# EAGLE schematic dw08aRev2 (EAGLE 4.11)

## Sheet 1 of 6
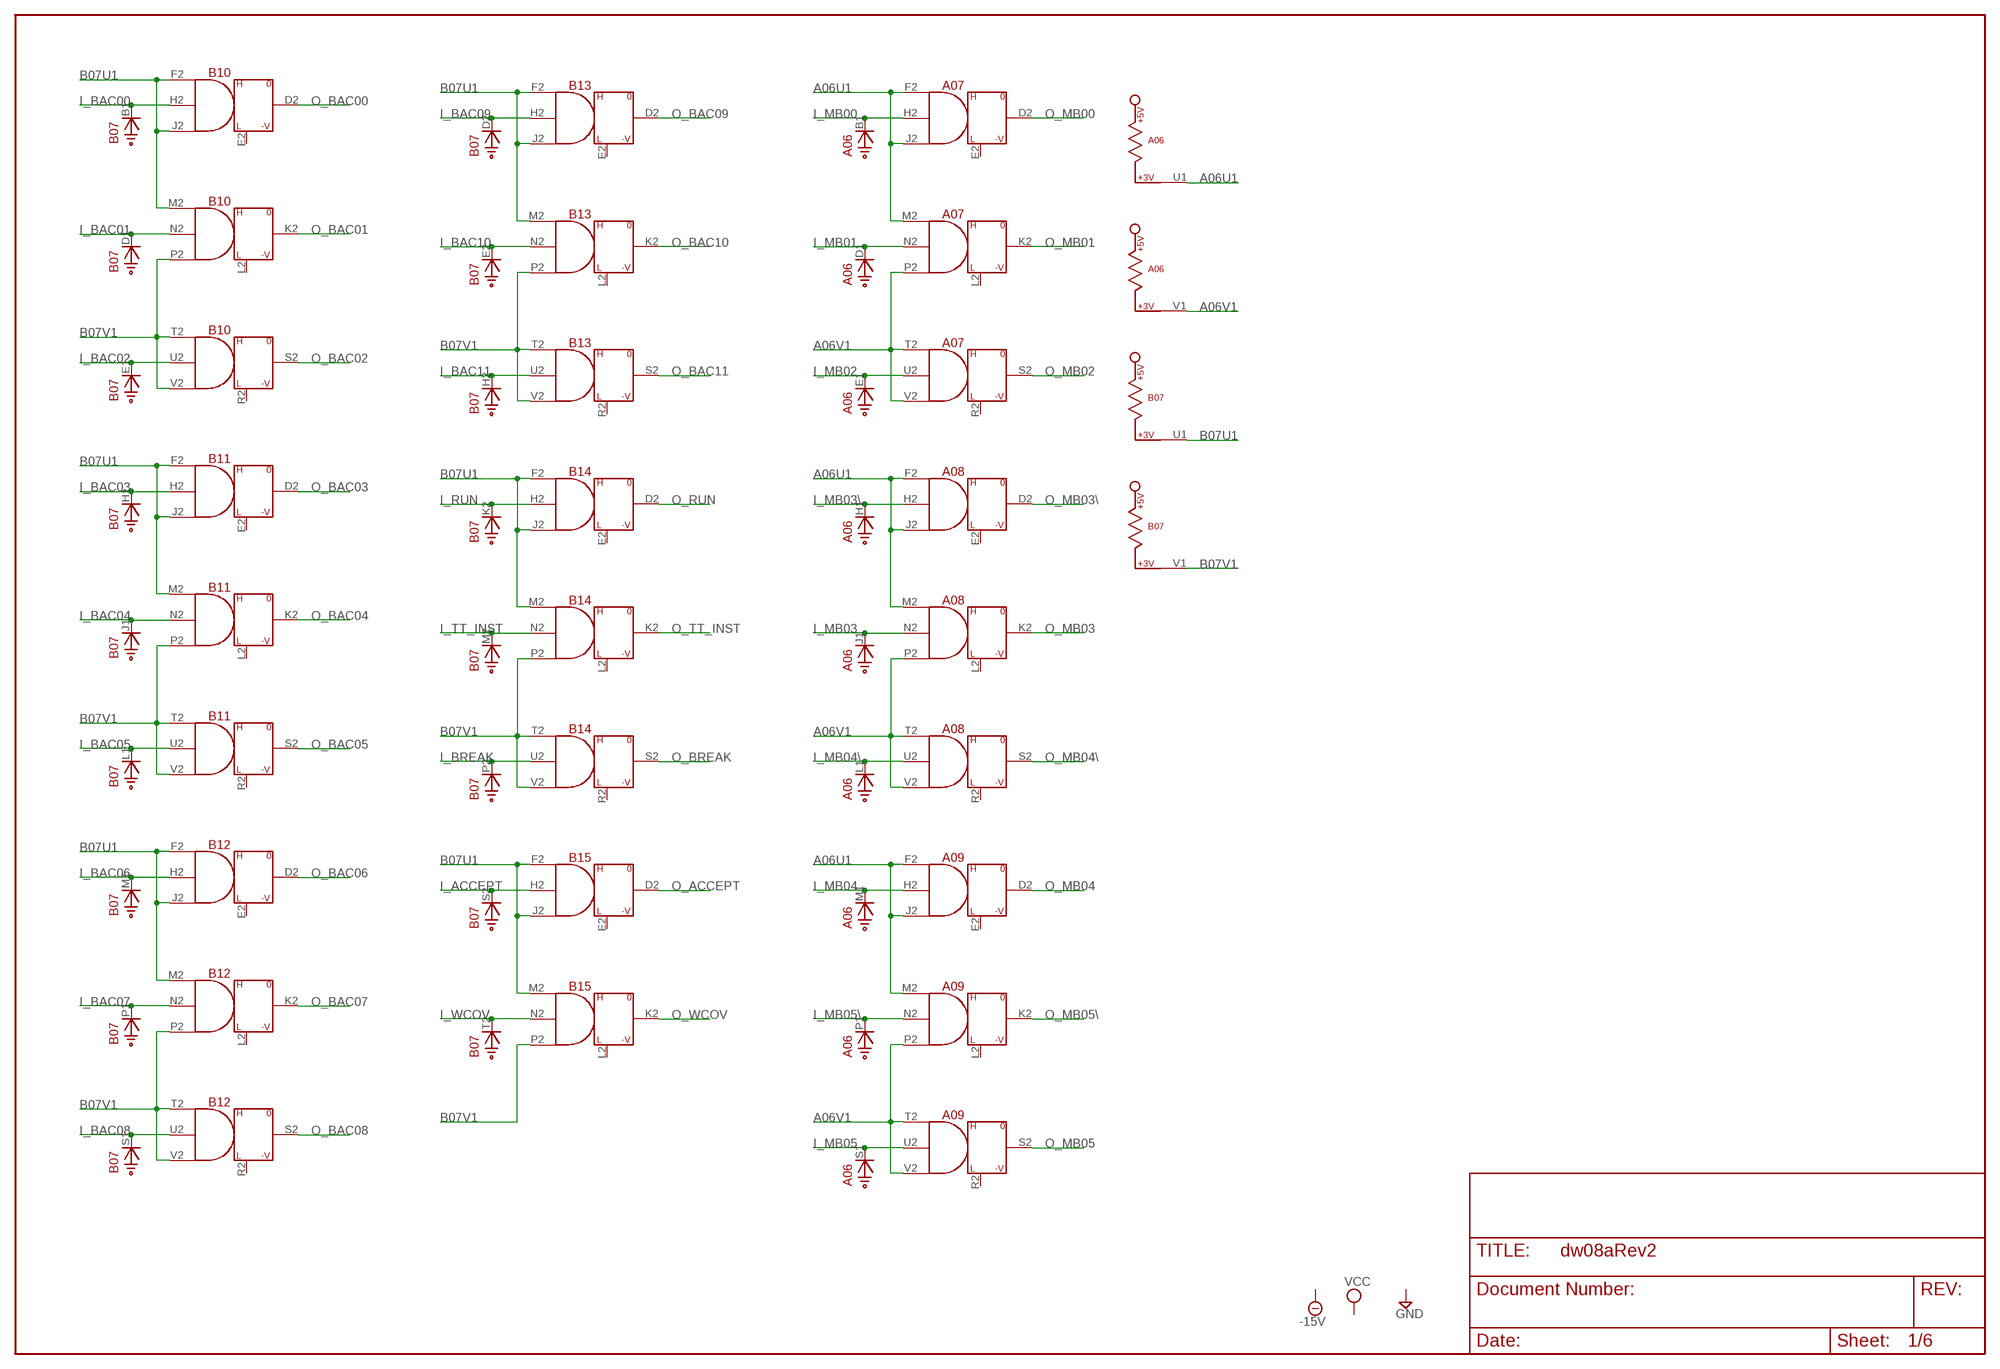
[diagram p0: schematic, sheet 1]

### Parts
A06  M907  [H807]
A07  M651  [H807]
A08  M651  [H807]
A09  M651  [H807]
B07  M907  [H807]
B10  M651  [H807]
B11  M651  [H807]
B12  M651  [H807]
B13  M651  [H807]
B14  M651  [H807]
B15  M651  [H807]

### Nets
A06U1: A06.U1 A07.F2(IN1) A07.J2(IN3) A07.M2(IN1) A08.F2(IN1) A08.J2(IN3) A08.M2(IN1) A09.F2(IN1) A09.J2(IN3) A09.M2(IN1) ; also sheet 2
A06V1: A06.V1 A07.P2(IN3) A07.T2(IN1) A07.V2(IN3) A08.P2(IN3) A08.T2(IN1) A08.V2(IN3) A09.P2(IN3) A09.T2(IN1) A09.V2(IN3) ; also sheet 2
B07U1: B07.U1 B10.F2(IN1) B10.J2(IN3) B10.M2(IN1) B11.F2(IN1) B11.J2(IN3) B11.M2(IN1) B12.F2(IN1) B12.J2(IN3) B12.M2(IN1) B13.F2(IN1) B13.J2(IN3) B13.M2(IN1) B14.F2(IN1) B14.J2(IN3) B14.M2(IN1) B15.F2(IN1) B15.J2(IN3) B15.M2(IN1) ; also sheet 2
B07V1: B07.V1 B10.P2(IN3) B10.T2(IN1) B10.V2(IN3) B11.P2(IN3) B11.T2(IN1) B11.V2(IN3) B12.P2(IN3) B12.T2(IN1) B12.V2(IN3) B13.P2(IN3) B13.T2(IN1) B13.V2(IN3) B14.P2(IN3) B14.T2(IN1) B14.V2(IN3) B15.P2(IN3)
I_ACCEPT: B07.S2(CATHODE) B15.H2(IN2) ; also sheet 6
I_BAC00: B07.B1(CATHODE) B10.H2(IN2) ; also sheet 6
I_BAC01: B07.D1(CATHODE) B10.N2(IN2) ; also sheet 6
I_BAC02: B07.E1(CATHODE) B10.U2(IN2) ; also sheet 6
I_BAC03: B07.H1(CATHODE) B11.H2(IN2) ; also sheet 6
I_BAC04: B07.J1(CATHODE) B11.N2(IN2) ; also sheet 6
I_BAC05: B07.L1(CATHODE) B11.U2(IN2) ; also sheet 6
I_BAC06: B07.M1(CATHODE) B12.H2(IN2) ; also sheet 6
I_BAC07: B07.P1(CATHODE) B12.N2(IN2) ; also sheet 6
I_BAC08: B07.S1(CATHODE) B12.U2(IN2) ; also sheet 6
I_BAC09: B07.D2(CATHODE) B13.H2(IN2) ; also sheet 6
I_BAC10: B07.E2(CATHODE) B13.N2(IN2) ; also sheet 6
I_BAC11: B07.H2(CATHODE) B13.U2(IN2) ; also sheet 6
I_BREAK: B07.P2(CATHODE) B14.U2(IN2) ; also sheet 4,6
I_MB00: A06.B1(CATHODE) A07.H2(IN2) ; also sheet 6
I_MB01: A06.D1(CATHODE) A07.N2(IN2) ; also sheet 6
I_MB02: A06.E1(CATHODE) A07.U2(IN2) ; also sheet 6
I_MB03: A06.J1(CATHODE) A08.N2(IN2) ; also sheet 6
I_MB03\: A06.H1(CATHODE) A08.H2(IN2) ; also sheet 6
I_MB04: A06.M1(CATHODE) A09.H2(IN2) ; also sheet 6
I_MB04\: A06.L1(CATHODE) A08.U2(IN2) ; also sheet 6
I_MB05: A06.S1(CATHODE) A09.U2(IN2) ; also sheet 6
I_MB05\: A06.P1(CATHODE) A09.N2(IN2) ; also sheet 6
I_RUN: B07.K2(CATHODE) B14.H2(IN2) ; also sheet 6
I_TT_INST: B07.M2(CATHODE) B14.N2(IN2) ; also sheet 6
I_WCOV: B07.T2(CATHODE) B15.N2(IN2) ; also sheet 6
O_ACCEPT: B15.D2(OUT) ; also sheet 5
O_BAC00: B10.D2(OUT) ; also sheet 5
O_BAC01: B10.K2(OUT) ; also sheet 5
O_BAC02: B10.S2(OUT) ; also sheet 5
O_BAC03: B11.D2(OUT) ; also sheet 5
O_BAC04: B11.K2(OUT) ; also sheet 5
O_BAC05: B11.S2(OUT) ; also sheet 5
O_BAC06: B12.D2(OUT) ; also sheet 5
O_BAC07: B12.K2(OUT) ; also sheet 5
O_BAC08: B12.S2(OUT) ; also sheet 5
O_BAC09: B13.D2(OUT) ; also sheet 5
O_BAC10: B13.K2(OUT) ; also sheet 5
O_BAC11: B13.S2(OUT) ; also sheet 5
O_BREAK: B14.S2(OUT) ; also sheet 5
O_MB00: A07.D2(OUT) ; also sheet 5
O_MB01: A07.K2(OUT) ; also sheet 5
O_MB02: A07.S2(OUT) ; also sheet 5
O_MB03: A08.K2(OUT) ; also sheet 5
O_MB03\: A08.D2(OUT) ; also sheet 5
O_MB04: A09.D2(OUT) ; also sheet 5
O_MB04\: A08.S2(OUT) ; also sheet 5
O_MB05: A09.S2(OUT) ; also sheet 5
O_MB05\: A09.K2(OUT) ; also sheet 5
O_RUN: B14.D2(OUT) ; also sheet 5
O_TT_INST: B14.K2(OUT) ; also sheet 5
O_WCOV: B15.K2(OUT) ; also sheet 5
Unconnected: A07.E2(SLOW) A07.L2(SLOW) A07.R2(SLOW) A08.E2(SLOW) A08.L2(SLOW) A08.R2(SLOW) A09.E2(SLOW) A09.L2(SLOW) A09.R2(SLOW) B07.V2(CATHODE) B10.E2(SLOW) B10.L2(SLOW) B10.R2(SLOW) B11.E2(SLOW) B11.L2(SLOW) B11.R2(SLOW) B12.E2(SLOW) B12.L2(SLOW) B12.R2(SLOW) B13.E2(SLOW) B13.L2(SLOW) B13.R2(SLOW) B14.E2(SLOW) B14.L2(SLOW) B14.R2(SLOW) B15.E2(SLOW) B15.L2(SLOW) B15.R2(SLOW) B15.S2(OUT) B15.T2(IN1) B15.U2(IN2) B15.V2(IN3)

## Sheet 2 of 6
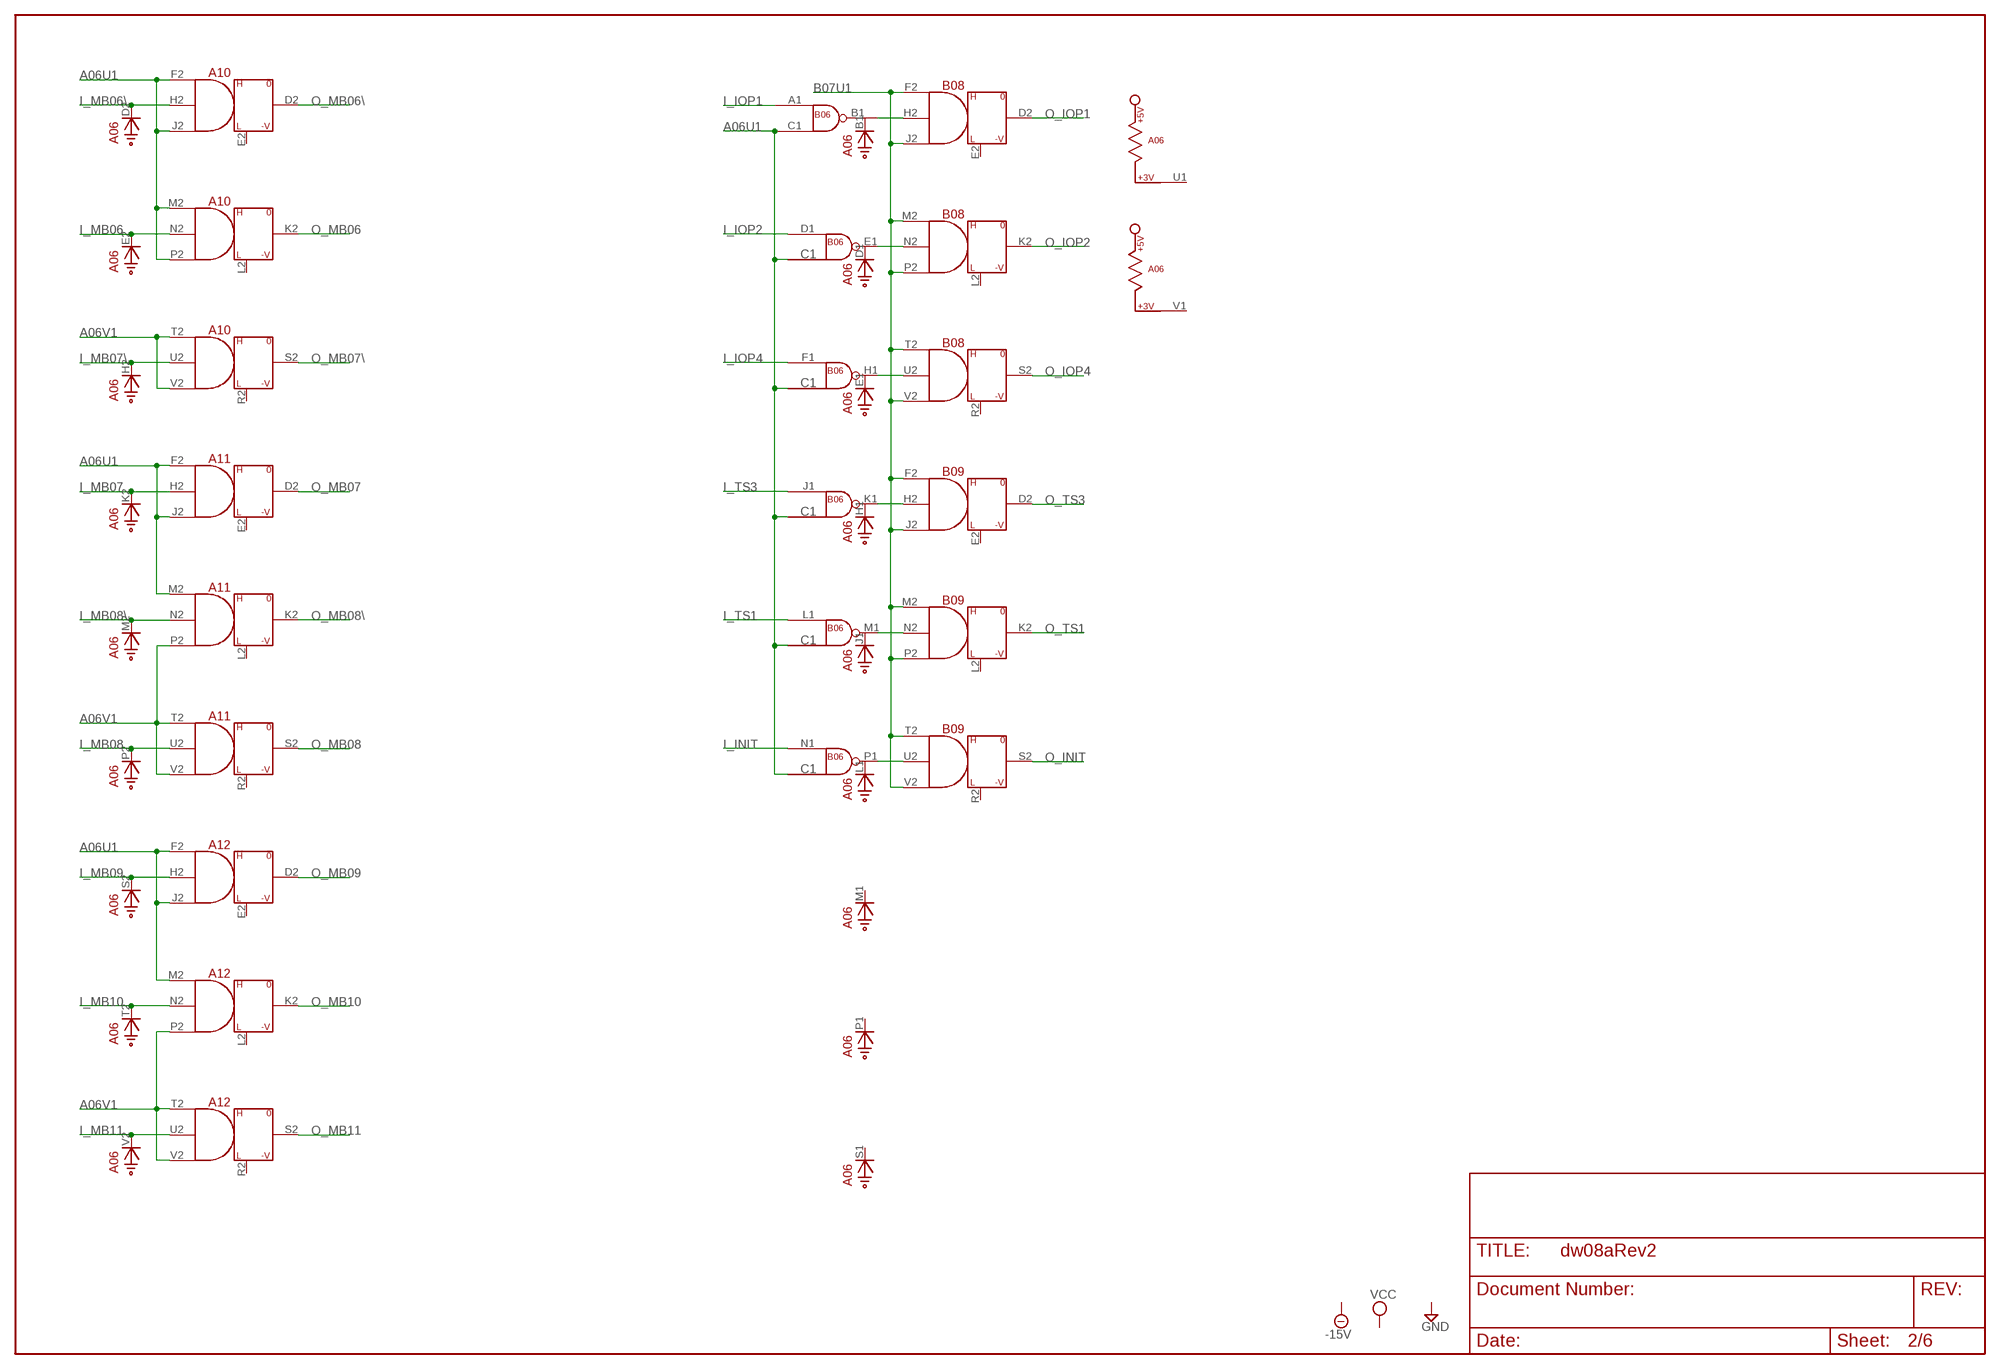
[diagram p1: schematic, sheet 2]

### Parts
A10  M651  [H807]
A11  M651  [H807]
A12  M651  [H807]
B06  M101  [H807]
B08  M651  [H807]
B09  M651  [H807]

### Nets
A06U1: A10.F2(IN1) A10.J2(IN3) A10.M2(IN1) A10.P2(IN3) A11.F2(IN1) A11.J2(IN3) A11.M2(IN1) A12.F2(IN1) A12.J2(IN3) A12.M2(IN1) B06.C1(IN2) ; also sheet 1
A06V1: A10.T2(IN1) A10.V2(IN3) A11.P2(IN3) A11.T2(IN1) A11.V2(IN3) A12.P2(IN3) A12.T2(IN1) A12.V2(IN3) ; also sheet 1
B07U1: B08.F2(IN1) B08.J2(IN3) B08.M2(IN1) B08.P2(IN3) B08.T2(IN1) B08.V2(IN3) B09.F2(IN1) B09.J2(IN3) B09.M2(IN1) B09.P2(IN3) B09.T2(IN1) B09.V2(IN3) ; also sheet 1
I_INIT: B06.N1(IN) ; also sheet 6
I_IOP1: B06.A1(IN1) ; also sheet 6
I_IOP2: B06.D1(IN) ; also sheet 6
I_IOP4: B06.F1(IN) ; also sheet 6
I_MB06: A06.E2(CATHODE) A10.N2(IN2) ; also sheet 6
I_MB06\: A06.D2(CATHODE) A10.H2(IN2) ; also sheet 6
I_MB07: A06.K2(CATHODE) A11.H2(IN2) ; also sheet 6
I_MB07\: A06.H2(CATHODE) A10.U2(IN2) ; also sheet 6
I_MB08: A06.P2(CATHODE) A11.U2(IN2) ; also sheet 6
I_MB08\: A06.M2(CATHODE) A11.N2(IN2) ; also sheet 6
I_MB09: A06.S2(CATHODE) A12.H2(IN2) ; also sheet 6
I_MB10: A06.T2(CATHODE) A12.N2(IN2) ; also sheet 6
I_MB11: A06.V2(CATHODE) A12.U2(IN2) ; also sheet 6
I_TS1: B06.L1(IN) ; also sheet 6
I_TS3: B06.J1(IN) ; also sheet 6
N$1: B06.B1(OUT) B08.H2(IN2)
N$2: B06.E1(OUT) B08.N2(IN2)
N$3: B06.H1(OUT) B08.U2(IN2)
N$4: B06.K1(OUT) B09.H2(IN2)
N$5: B06.M1(OUT) B09.N2(IN2)
N$6: B06.P1(OUT) B09.U2(IN2)
O_INIT: B09.S2(OUT) ; also sheet 5
O_IOP1: B08.D2(OUT) ; also sheet 5
O_IOP2: B08.K2(OUT) ; also sheet 5
O_IOP4: B08.S2(OUT) ; also sheet 5
O_MB06: A10.K2(OUT) ; also sheet 5
O_MB06\: A10.D2(OUT) ; also sheet 5
O_MB07: A11.D2(OUT) ; also sheet 5
O_MB07\: A10.S2(OUT) ; also sheet 5
O_MB08: A11.S2(OUT) ; also sheet 5
O_MB08\: A11.K2(OUT) ; also sheet 5
O_MB09: A12.D2(OUT) ; also sheet 5
O_MB10: A12.K2(OUT) ; also sheet 5
O_MB11: A12.S2(OUT) ; also sheet 5
O_TS1: B09.K2(OUT) ; also sheet 5
O_TS3: B09.D2(OUT) ; also sheet 5
Unconnected: A10.E2(SLOW) A10.L2(SLOW) A10.R2(SLOW) A11.E2(SLOW) A11.L2(SLOW) A11.R2(SLOW) A12.E2(SLOW) A12.L2(SLOW) A12.R2(SLOW) B06.E2(IN) B06.F2(OUT) B06.H2(IN) B06.J2(OUT) B06.K2(IN) B06.L2(OUT) B06.M2(IN) B06.N2(OUT) B06.P2(IN) B06.R1(IN) B06.R2(OUT) B06.S1(OUT) B06.S2(IN) B06.T2(OUT) B06.U1(OUT) B06.U2(IN) B06.V1(IN) B06.V2(OUT) B08.E2(SLOW) B08.L2(SLOW) B08.R2(SLOW) B09.E2(SLOW) B09.L2(SLOW) B09.R2(SLOW)

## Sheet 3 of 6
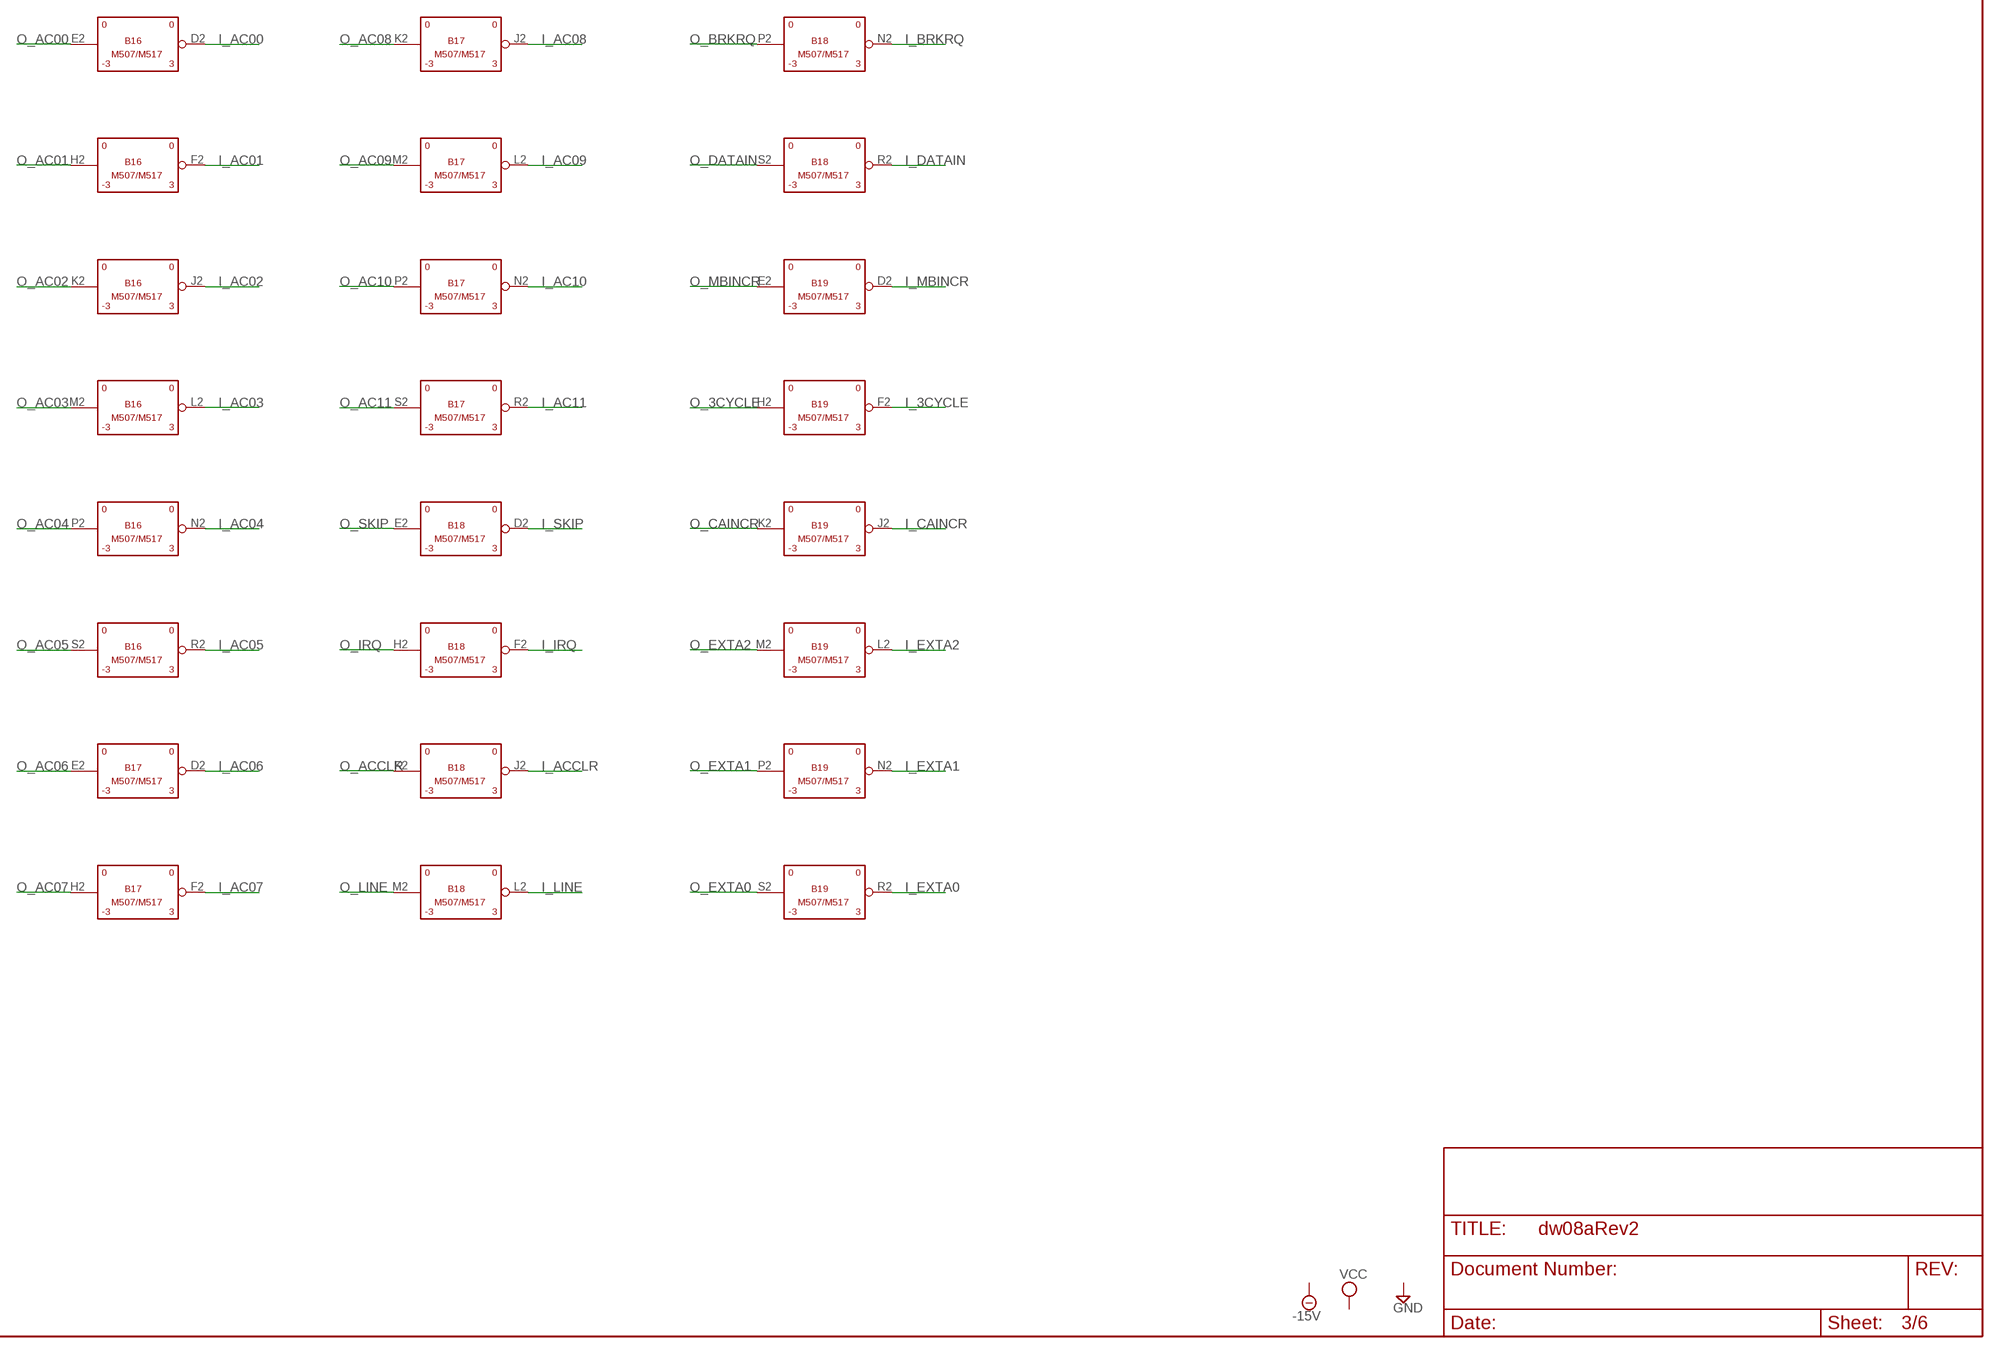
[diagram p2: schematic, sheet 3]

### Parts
B16  M517  [H807]
B17  M517  [H807]
B18  M517  [H807]
B19  M517  [H807]

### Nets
I_3CYCLE: B19.F2(OUT) ; also sheet 6
I_AC00: B16.D2(OUT) ; also sheet 6
I_AC01: B16.F2(OUT) ; also sheet 6
I_AC02: B16.J2(OUT) ; also sheet 6
I_AC03: B16.L2(OUT) ; also sheet 6
I_AC04: B16.N2(OUT) ; also sheet 6
I_AC05: B16.R2(OUT) ; also sheet 6
I_AC06: B17.D2(OUT) ; also sheet 6
I_AC07: B17.F2(OUT) ; also sheet 6
I_AC08: B17.J2(OUT) ; also sheet 6
I_AC09: B17.L2(OUT) ; also sheet 6
I_AC10: B17.N2(OUT) ; also sheet 6
I_AC11: B17.R2(OUT) ; also sheet 6
I_ACCLR: B18.J2(OUT) ; also sheet 6
I_BRKRQ: B18.N2(OUT) ; also sheet 6
I_CAINCR: B19.J2(OUT) ; also sheet 6
I_DATAIN: B18.R2(OUT) ; also sheet 6
I_EXTA0: B19.R2(OUT) ; also sheet 6
I_EXTA1: B19.N2(OUT) ; also sheet 6
I_EXTA2: B19.L2(OUT) ; also sheet 6
I_IRQ: B18.F2(OUT) ; also sheet 6
I_LINE: B18.L2(OUT) ; also sheet 6
I_MBINCR: B19.D2(OUT) ; also sheet 6
I_SKIP: B18.D2(OUT) ; also sheet 6
O_3CYCLE: B19.H2(IN) ; also sheet 5
O_AC00: B16.E2(IN) ; also sheet 5
O_AC01: B16.H2(IN) ; also sheet 5
O_AC02: B16.K2(IN) ; also sheet 5
O_AC03: B16.M2(IN) ; also sheet 5
O_AC04: B16.P2(IN) ; also sheet 5
O_AC05: B16.S2(IN) ; also sheet 5
O_AC06: B17.E2(IN) ; also sheet 5
O_AC07: B17.H2(IN) ; also sheet 5
O_AC08: B17.K2(IN) ; also sheet 5
O_AC09: B17.M2(IN) ; also sheet 5
O_AC10: B17.P2(IN) ; also sheet 5
O_AC11: B17.S2(IN) ; also sheet 5
O_ACCLR: B18.K2(IN) ; also sheet 5
O_BRKRQ: B18.P2(IN) ; also sheet 5
O_CAINCR: B19.K2(IN) ; also sheet 5
O_DATAIN: B18.S2(IN) ; also sheet 5
O_EXTA0: B19.S2(IN) ; also sheet 5
O_EXTA1: B19.P2(IN) ; also sheet 5
O_EXTA2: B19.M2(IN) ; also sheet 5
O_IRQ: B18.H2(IN) ; also sheet 5
O_LINE: B18.M2(IN) ; also sheet 5
O_MBINCR: B19.E2(IN) ; also sheet 5
O_SKIP: B18.E2(IN) ; also sheet 5

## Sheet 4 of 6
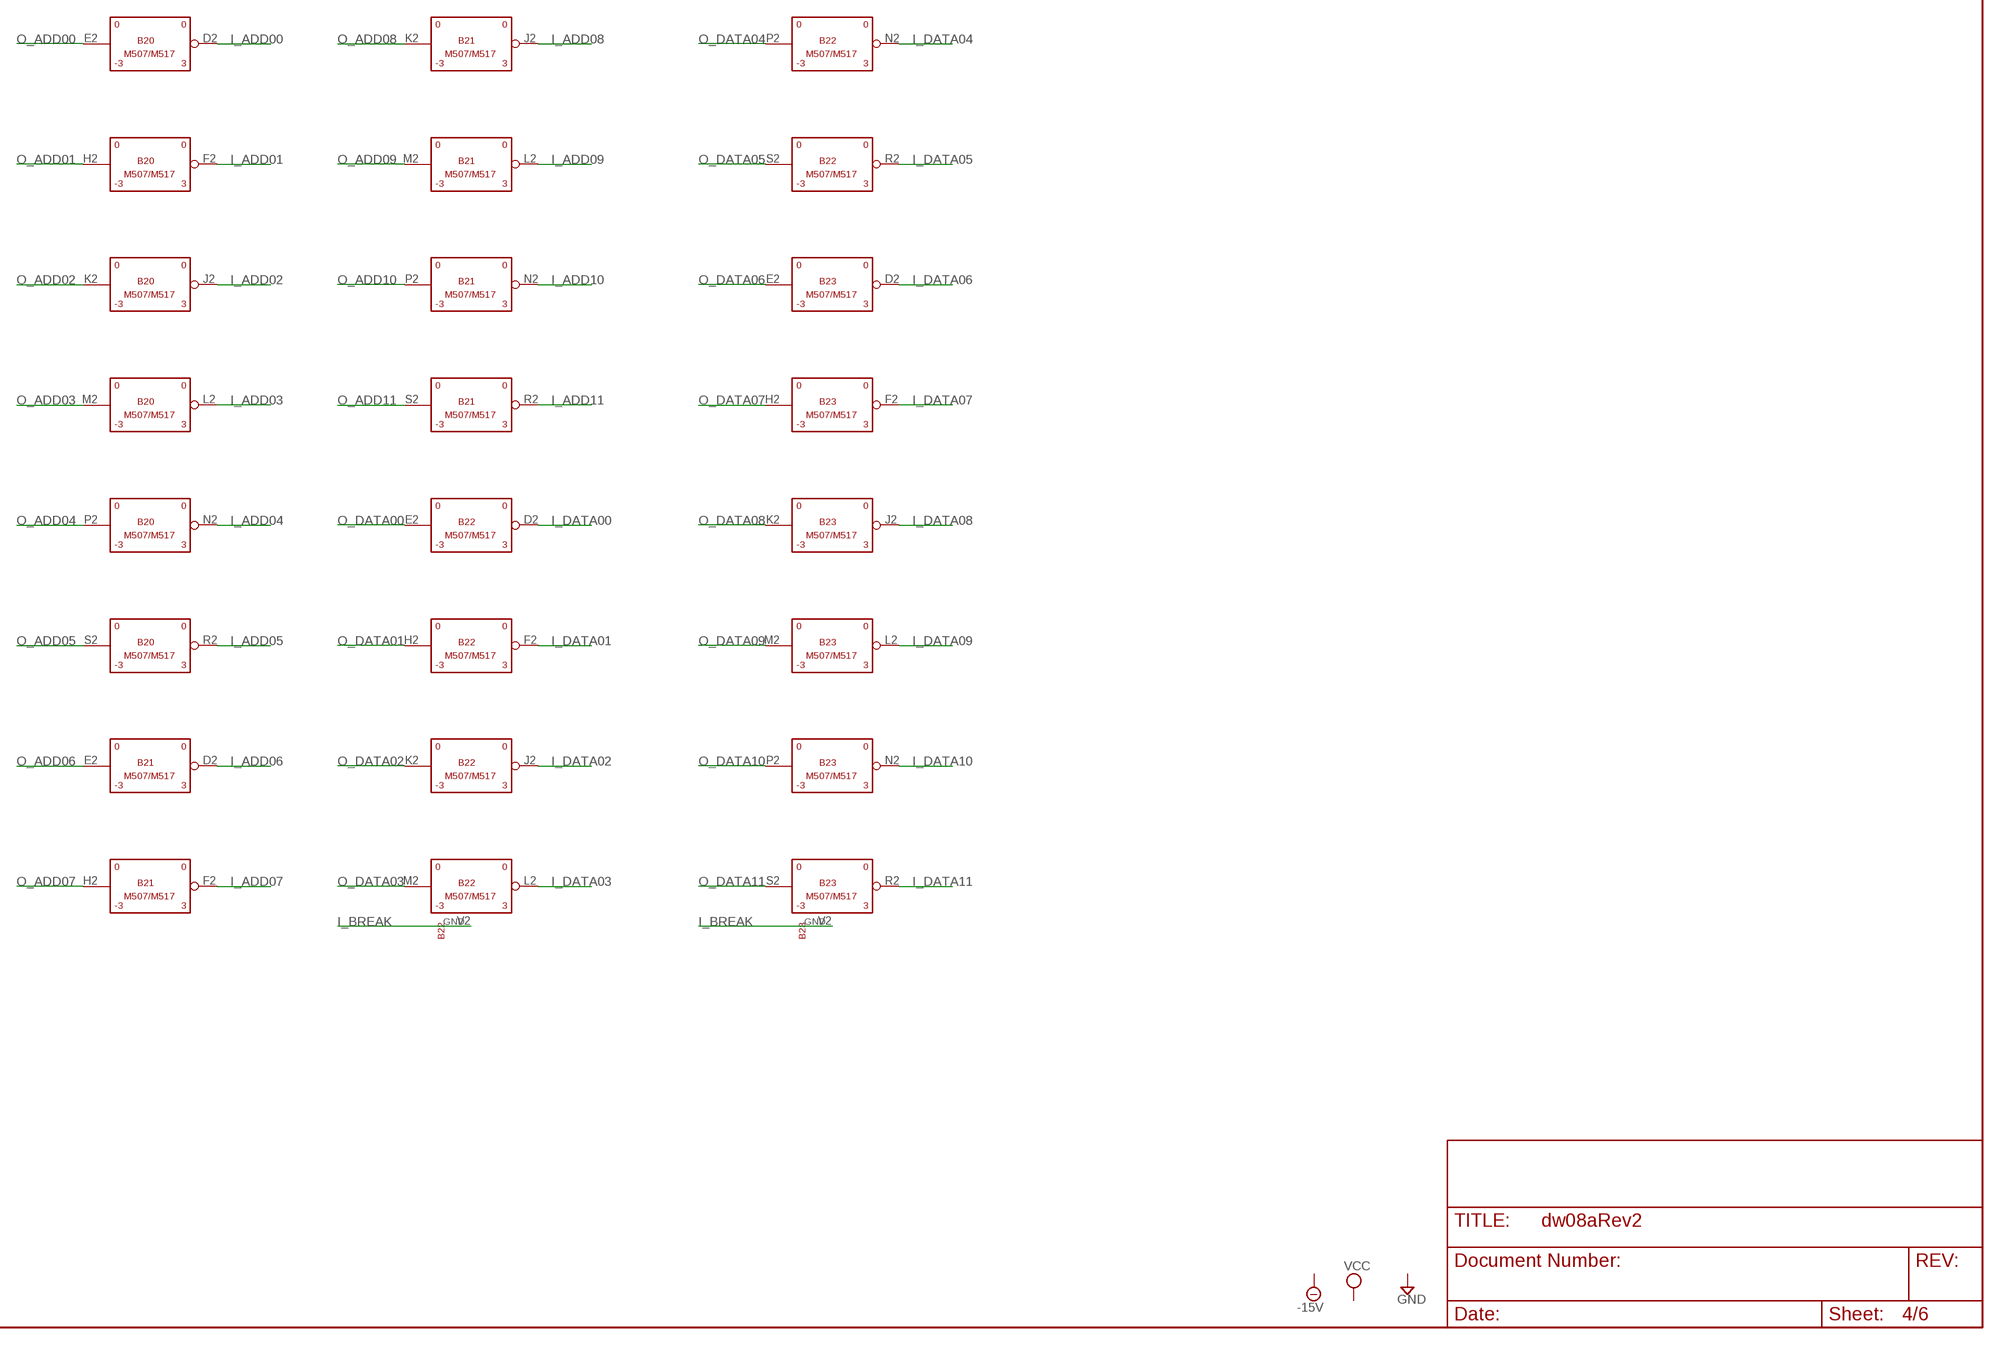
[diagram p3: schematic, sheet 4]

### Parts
B20  M517  [H807]
B21  M517  [H807]
B22  M517  [H807]
B23  M517  [H807]

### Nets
I_ADD00: B20.D2(OUT) ; also sheet 6
I_ADD01: B20.F2(OUT) ; also sheet 6
I_ADD02: B20.J2(OUT) ; also sheet 6
I_ADD03: B20.L2(OUT) ; also sheet 6
I_ADD04: B20.N2(OUT) ; also sheet 6
I_ADD05: B20.R2(OUT) ; also sheet 6
I_ADD06: B21.D2(OUT) ; also sheet 6
I_ADD07: B21.F2(OUT) ; also sheet 6
I_ADD08: B21.J2(OUT) ; also sheet 6
I_ADD09: B21.L2(OUT) ; also sheet 6
I_ADD10: B21.N2(OUT) ; also sheet 6
I_ADD11: B21.R2(OUT) ; also sheet 6
I_BREAK: B22.V2(V2:GND) B23.V2(V2:GND) ; also sheet 1,6
I_DATA00: B22.D2(OUT) ; also sheet 6
I_DATA01: B22.F2(OUT) ; also sheet 6
I_DATA02: B22.J2(OUT) ; also sheet 6
I_DATA03: B22.L2(OUT) ; also sheet 6
I_DATA04: B22.N2(OUT) ; also sheet 6
I_DATA05: B22.R2(OUT) ; also sheet 6
I_DATA06: B23.D2(OUT) ; also sheet 6
I_DATA07: B23.F2(OUT) ; also sheet 6
I_DATA08: B23.J2(OUT) ; also sheet 6
I_DATA09: B23.L2(OUT) ; also sheet 6
I_DATA10: B23.N2(OUT) ; also sheet 6
I_DATA11: B23.R2(OUT) ; also sheet 6
O_ADD00: B20.E2(IN) ; also sheet 5
O_ADD01: B20.H2(IN) ; also sheet 5
O_ADD02: B20.K2(IN) ; also sheet 5
O_ADD03: B20.M2(IN) ; also sheet 5
O_ADD04: B20.P2(IN) ; also sheet 5
O_ADD05: B20.S2(IN) ; also sheet 5
O_ADD06: B21.E2(IN) ; also sheet 5
O_ADD07: B21.H2(IN) ; also sheet 5
O_ADD08: B21.K2(IN) ; also sheet 5
O_ADD09: B21.M2(IN) ; also sheet 5
O_ADD10: B21.P2(IN) ; also sheet 5
O_ADD11: B21.S2(IN) ; also sheet 5
O_DATA00: B22.E2(IN) ; also sheet 5
O_DATA01: B22.H2(IN) ; also sheet 5
O_DATA02: B22.K2(IN) ; also sheet 5
O_DATA03: B22.M2(IN) ; also sheet 5
O_DATA04: B22.P2(IN) ; also sheet 5
O_DATA05: B22.S2(IN) ; also sheet 5
O_DATA06: B23.E2(IN) ; also sheet 5
O_DATA07: B23.H2(IN) ; also sheet 5
O_DATA08: B23.K2(IN) ; also sheet 5
O_DATA09: B23.M2(IN) ; also sheet 5
O_DATA10: B23.P2(IN) ; also sheet 5
O_DATA11: B23.S2(IN) ; also sheet 5

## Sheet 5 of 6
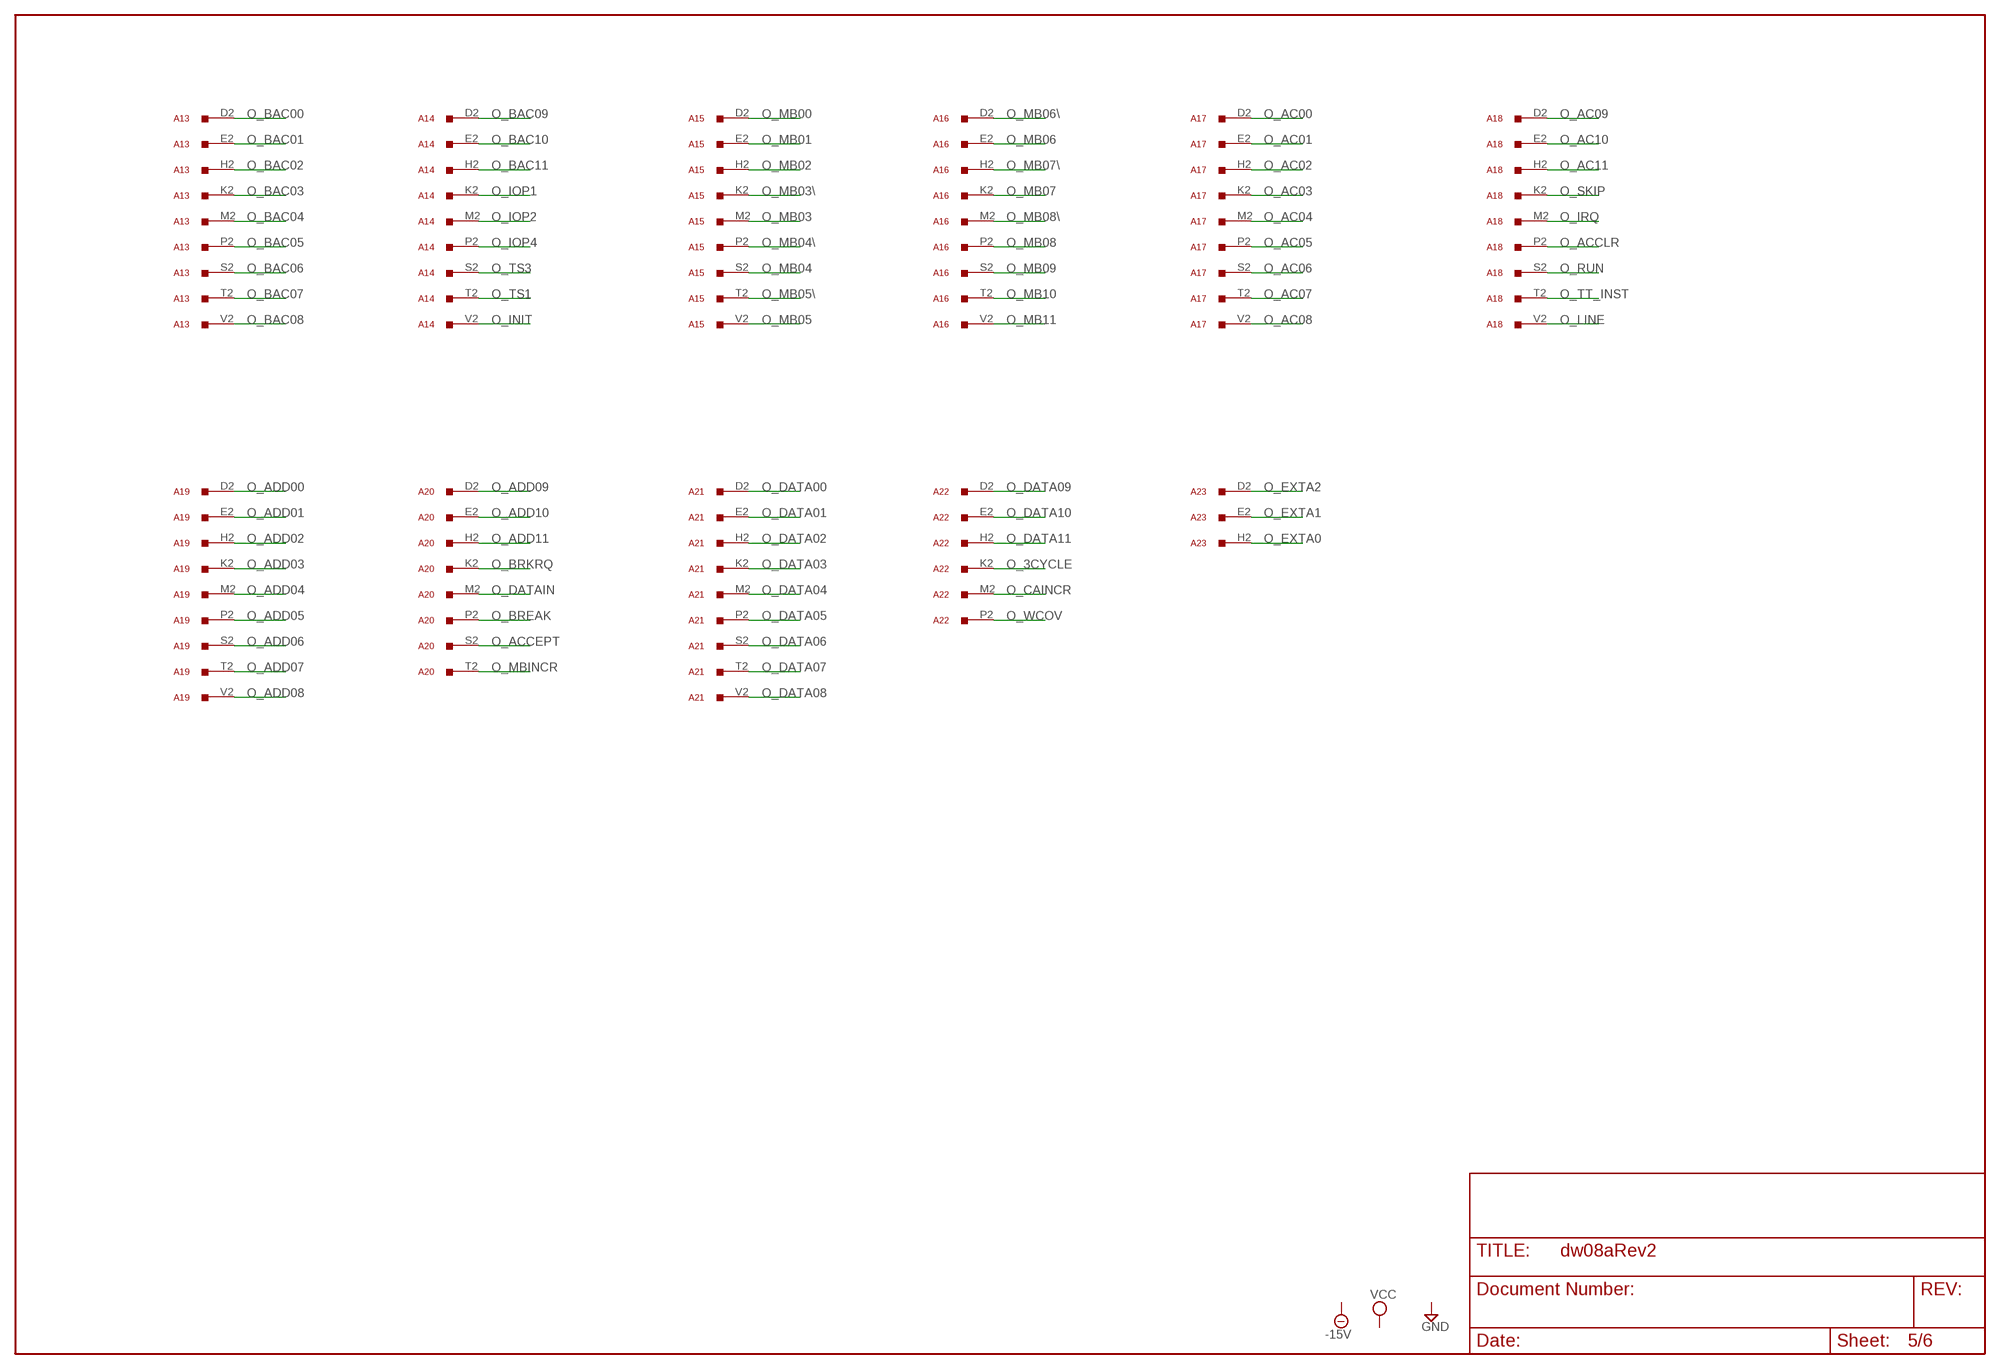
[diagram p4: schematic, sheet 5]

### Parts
A13  W011  [H807]
A14  W011  [H807]
A15  W011  [H807]
A16  W011  [H807]
A17  W011  [H807]
A18  W011  [H807]
A19  W011  [H807]
A20  W011  [H807]
A21  W011  [H807]
A22  W011  [H807]
A23  W011  [H807]

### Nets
O_3CYCLE: A22.K2 ; also sheet 3
O_AC00: A17.D2 ; also sheet 3
O_AC01: A17.E2 ; also sheet 3
O_AC02: A17.H2 ; also sheet 3
O_AC03: A17.K2 ; also sheet 3
O_AC04: A17.M2 ; also sheet 3
O_AC05: A17.P2 ; also sheet 3
O_AC06: A17.S2 ; also sheet 3
O_AC07: A17.T2 ; also sheet 3
O_AC08: A17.V2 ; also sheet 3
O_AC09: A18.D2 ; also sheet 3
O_AC10: A18.E2 ; also sheet 3
O_AC11: A18.H2 ; also sheet 3
O_ACCEPT: A20.S2 ; also sheet 1
O_ACCLR: A18.P2 ; also sheet 3
O_ADD00: A19.D2 ; also sheet 4
O_ADD01: A19.E2 ; also sheet 4
O_ADD02: A19.H2 ; also sheet 4
O_ADD03: A19.K2 ; also sheet 4
O_ADD04: A19.M2 ; also sheet 4
O_ADD05: A19.P2 ; also sheet 4
O_ADD06: A19.S2 ; also sheet 4
O_ADD07: A19.T2 ; also sheet 4
O_ADD08: A19.V2 ; also sheet 4
O_ADD09: A20.D2 ; also sheet 4
O_ADD10: A20.E2 ; also sheet 4
O_ADD11: A20.H2 ; also sheet 4
O_BAC00: A13.D2 ; also sheet 1
O_BAC01: A13.E2 ; also sheet 1
O_BAC02: A13.H2 ; also sheet 1
O_BAC03: A13.K2 ; also sheet 1
O_BAC04: A13.M2 ; also sheet 1
O_BAC05: A13.P2 ; also sheet 1
O_BAC06: A13.S2 ; also sheet 1
O_BAC07: A13.T2 ; also sheet 1
O_BAC08: A13.V2 ; also sheet 1
O_BAC09: A14.D2 ; also sheet 1
O_BAC10: A14.E2 ; also sheet 1
O_BAC11: A14.H2 ; also sheet 1
O_BREAK: A20.P2 ; also sheet 1
O_BRKRQ: A20.K2 ; also sheet 3
O_CAINCR: A22.M2 ; also sheet 3
O_DATA00: A21.D2 ; also sheet 4
O_DATA01: A21.E2 ; also sheet 4
O_DATA02: A21.H2 ; also sheet 4
O_DATA03: A21.K2 ; also sheet 4
O_DATA04: A21.M2 ; also sheet 4
O_DATA05: A21.P2 ; also sheet 4
O_DATA06: A21.S2 ; also sheet 4
O_DATA07: A21.T2 ; also sheet 4
O_DATA08: A21.V2 ; also sheet 4
O_DATA09: A22.D2 ; also sheet 4
O_DATA10: A22.E2 ; also sheet 4
O_DATA11: A22.H2 ; also sheet 4
O_DATAIN: A20.M2 ; also sheet 3
O_EXTA0: A23.H2 ; also sheet 3
O_EXTA1: A23.E2 ; also sheet 3
O_EXTA2: A23.D2 ; also sheet 3
O_INIT: A14.V2 ; also sheet 2
O_IOP1: A14.K2 ; also sheet 2
O_IOP2: A14.M2 ; also sheet 2
O_IOP4: A14.P2 ; also sheet 2
O_IRQ: A18.M2 ; also sheet 3
O_LINE: A18.V2 ; also sheet 3
O_MB00: A15.D2 ; also sheet 1
O_MB01: A15.E2 ; also sheet 1
O_MB02: A15.H2 ; also sheet 1
O_MB03: A15.M2 ; also sheet 1
O_MB03\: A15.K2 ; also sheet 1
O_MB04: A15.S2 ; also sheet 1
O_MB04\: A15.P2 ; also sheet 1
O_MB05: A15.V2 ; also sheet 1
O_MB05\: A15.T2 ; also sheet 1
O_MB06: A16.E2 ; also sheet 2
O_MB06\: A16.D2 ; also sheet 2
O_MB07: A16.K2 ; also sheet 2
O_MB07\: A16.H2 ; also sheet 2
O_MB08: A16.P2 ; also sheet 2
O_MB08\: A16.M2 ; also sheet 2
O_MB09: A16.S2 ; also sheet 2
O_MB10: A16.T2 ; also sheet 2
O_MB11: A16.V2 ; also sheet 2
O_MBINCR: A20.T2 ; also sheet 3
O_RUN: A18.S2 ; also sheet 1
O_SKIP: A18.K2 ; also sheet 3
O_TS1: A14.T2 ; also sheet 2
O_TS3: A14.S2 ; also sheet 2
O_TT_INST: A18.T2 ; also sheet 1
O_WCOV: A22.P2 ; also sheet 1
Unconnected: A20.V2 A22.S2 A22.T2 A22.V2 A23.K2 A23.M2 A23.P2 A23.S2 A23.T2 A23.V2

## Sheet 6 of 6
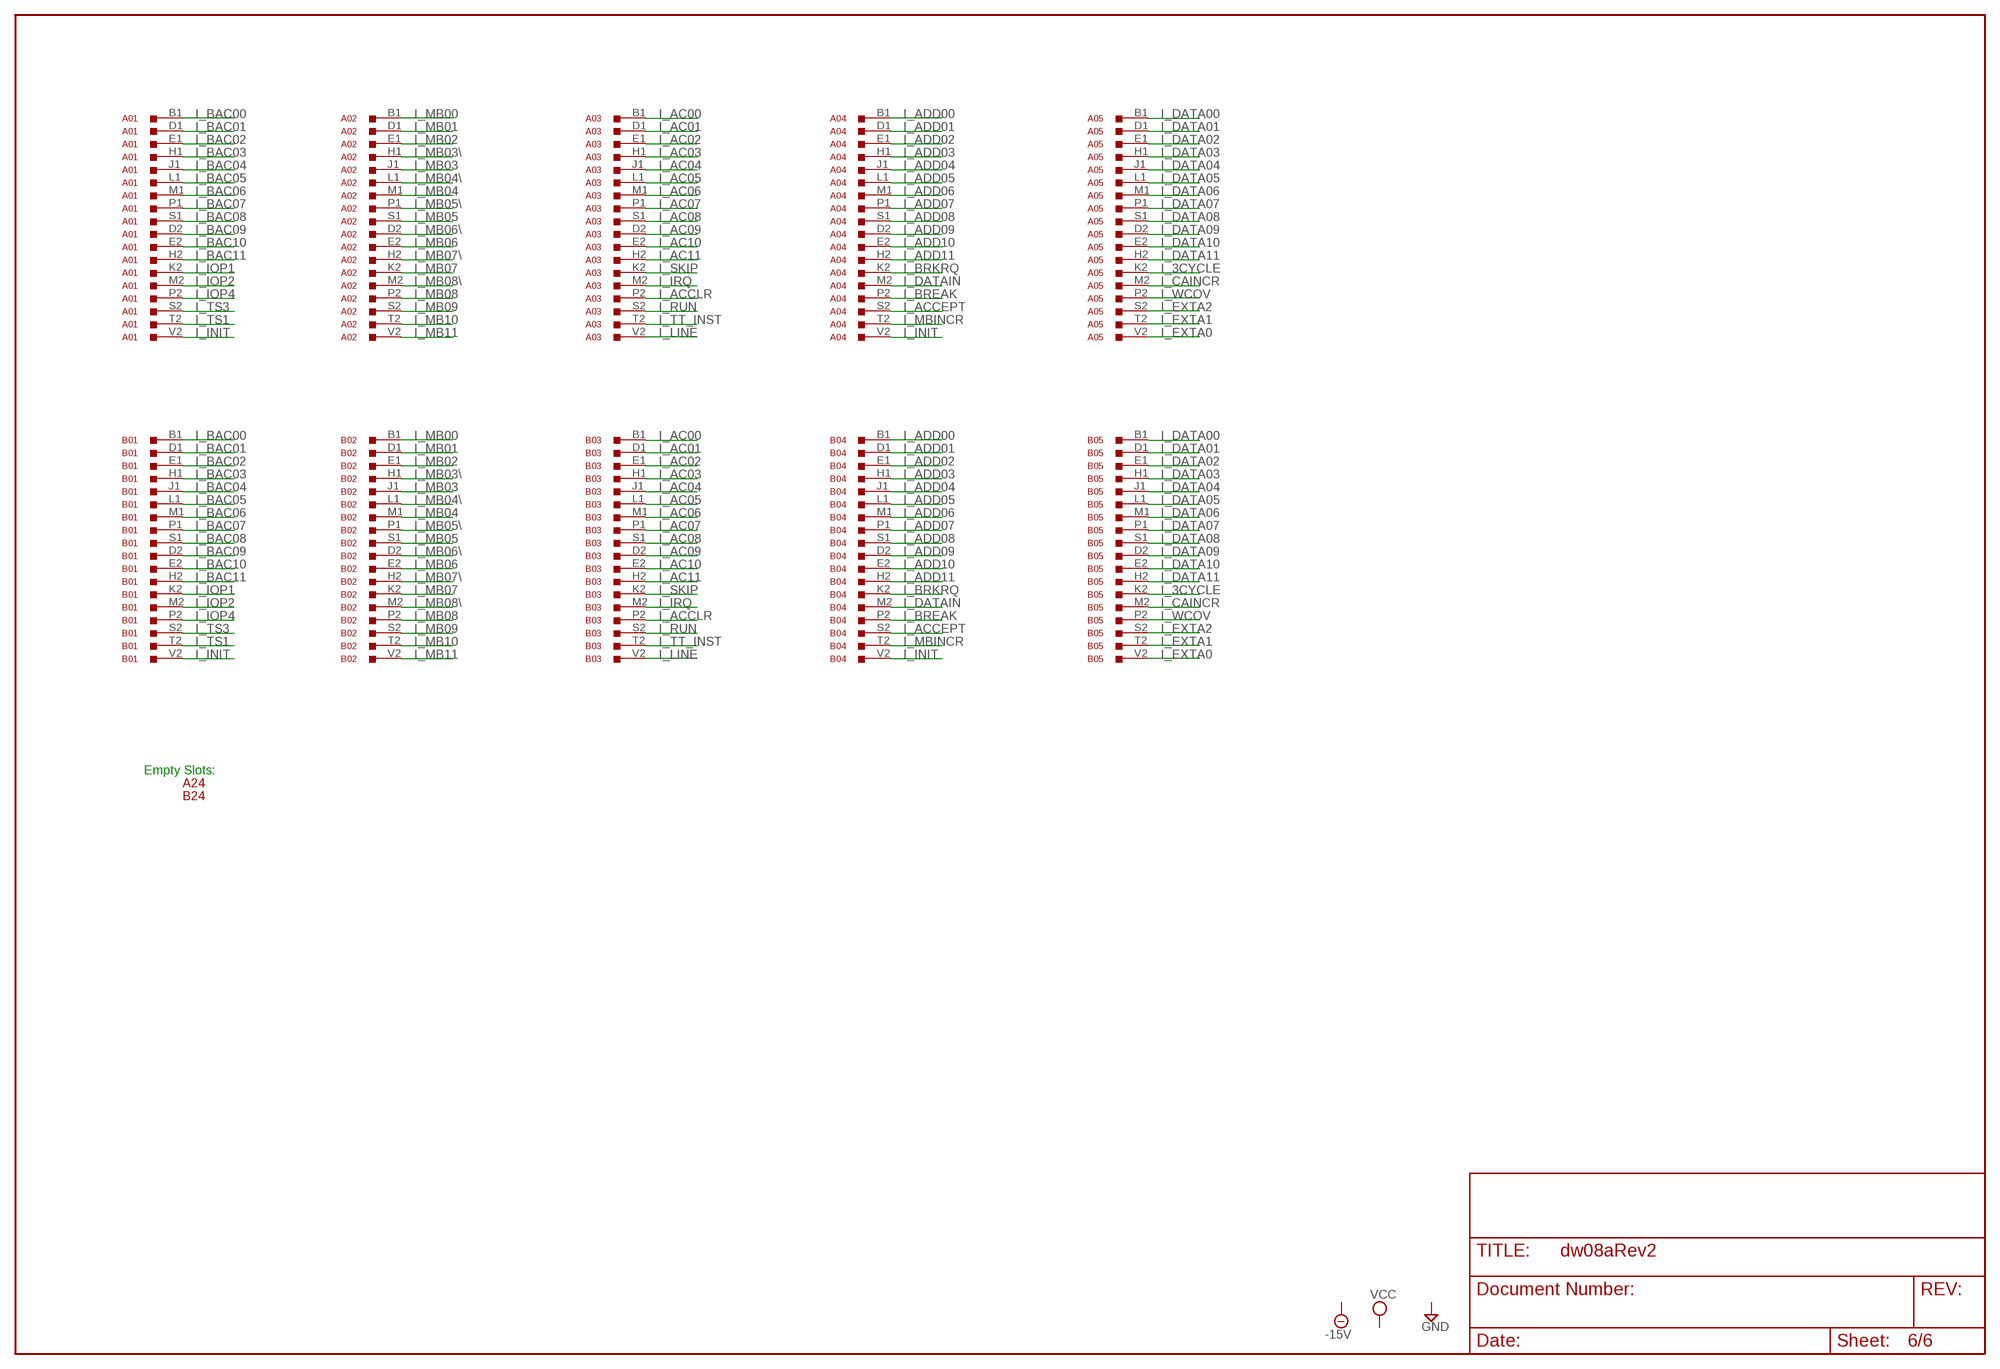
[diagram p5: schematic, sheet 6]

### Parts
A01  M903  [H807]
A02  M903  [H807]
A03  M903  [H807]
A04  M903  [H807]
A05  M903  [H807]
A24  H807  [H807]
B01  M903  [H807]
B02  M903  [H807]
B03  M903  [H807]
B04  M903  [H807]
B05  M903  [H807]
B24  H807  [H807]

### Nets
I_3CYCLE: A05.K2 B05.K2 ; also sheet 3
I_AC00: A03.B1 B03.B1 ; also sheet 3
I_AC01: A03.D1 B03.D1 ; also sheet 3
I_AC02: A03.E1 B03.E1 ; also sheet 3
I_AC03: A03.H1 B03.H1 ; also sheet 3
I_AC04: A03.J1 B03.J1 ; also sheet 3
I_AC05: A03.L1 B03.L1 ; also sheet 3
I_AC06: A03.M1 B03.M1 ; also sheet 3
I_AC07: A03.P1 B03.P1 ; also sheet 3
I_AC08: A03.S1 B03.S1 ; also sheet 3
I_AC09: A03.D2 B03.D2 ; also sheet 3
I_AC10: A03.E2 B03.E2 ; also sheet 3
I_AC11: A03.H2 B03.H2 ; also sheet 3
I_ACCEPT: A04.S2 B04.S2 ; also sheet 1
I_ACCLR: A03.P2 B03.P2 ; also sheet 3
I_ADD00: A04.B1 B04.B1 ; also sheet 4
I_ADD01: A04.D1 B04.D1 ; also sheet 4
I_ADD02: A04.E1 B04.E1 ; also sheet 4
I_ADD03: A04.H1 B04.H1 ; also sheet 4
I_ADD04: A04.J1 B04.J1 ; also sheet 4
I_ADD05: A04.L1 B04.L1 ; also sheet 4
I_ADD06: A04.M1 B04.M1 ; also sheet 4
I_ADD07: A04.P1 B04.P1 ; also sheet 4
I_ADD08: A04.S1 B04.S1 ; also sheet 4
I_ADD09: A04.D2 B04.D2 ; also sheet 4
I_ADD10: A04.E2 B04.E2 ; also sheet 4
I_ADD11: A04.H2 B04.H2 ; also sheet 4
I_BAC00: A01.B1 B01.B1 ; also sheet 1
I_BAC01: A01.D1 B01.D1 ; also sheet 1
I_BAC02: A01.E1 B01.E1 ; also sheet 1
I_BAC03: A01.H1 B01.H1 ; also sheet 1
I_BAC04: A01.J1 B01.J1 ; also sheet 1
I_BAC05: A01.L1 B01.L1 ; also sheet 1
I_BAC06: A01.M1 B01.M1 ; also sheet 1
I_BAC07: A01.P1 B01.P1 ; also sheet 1
I_BAC08: A01.S1 B01.S1 ; also sheet 1
I_BAC09: A01.D2 B01.D2 ; also sheet 1
I_BAC10: A01.E2 B01.E2 ; also sheet 1
I_BAC11: A01.H2 B01.H2 ; also sheet 1
I_BREAK: A04.P2 B04.P2 ; also sheet 1,4
I_BRKRQ: A04.K2 B04.K2 ; also sheet 3
I_CAINCR: A05.M2 B05.M2 ; also sheet 3
I_DATA00: A05.B1 B05.B1 ; also sheet 4
I_DATA01: A05.D1 B05.D1 ; also sheet 4
I_DATA02: A05.E1 B05.E1 ; also sheet 4
I_DATA03: A05.H1 B05.H1 ; also sheet 4
I_DATA04: A05.J1 B05.J1 ; also sheet 4
I_DATA05: A05.L1 B05.L1 ; also sheet 4
I_DATA06: A05.M1 B05.M1 ; also sheet 4
I_DATA07: A05.P1 B05.P1 ; also sheet 4
I_DATA08: A05.S1 B05.S1 ; also sheet 4
I_DATA09: A05.D2 B05.D2 ; also sheet 4
I_DATA10: A05.E2 B05.E2 ; also sheet 4
I_DATA11: A05.H2 B05.H2 ; also sheet 4
I_DATAIN: A04.M2 B04.M2 ; also sheet 3
I_EXTA0: A05.V2 B05.V2 ; also sheet 3
I_EXTA1: A05.T2 B05.T2 ; also sheet 3
I_EXTA2: A05.S2 B05.S2 ; also sheet 3
I_INIT: A01.V2 A04.V2 B01.V2 B04.V2 ; also sheet 2
I_IOP1: A01.K2 B01.K2 ; also sheet 2
I_IOP2: A01.M2 B01.M2 ; also sheet 2
I_IOP4: A01.P2 B01.P2 ; also sheet 2
I_IRQ: A03.M2 B03.M2 ; also sheet 3
I_LINE: A03.V2 B03.V2 ; also sheet 3
I_MB00: A02.B1 B02.B1 ; also sheet 1
I_MB01: A02.D1 B02.D1 ; also sheet 1
I_MB02: A02.E1 B02.E1 ; also sheet 1
I_MB03: A02.J1 B02.J1 ; also sheet 1
I_MB03\: A02.H1 B02.H1 ; also sheet 1
I_MB04: A02.M1 B02.M1 ; also sheet 1
I_MB04\: A02.L1 B02.L1 ; also sheet 1
I_MB05: A02.S1 B02.S1 ; also sheet 1
I_MB05\: A02.P1 B02.P1 ; also sheet 1
I_MB06: A02.E2 B02.E2 ; also sheet 2
I_MB06\: A02.D2 B02.D2 ; also sheet 2
I_MB07: A02.K2 B02.K2 ; also sheet 2
I_MB07\: A02.H2 B02.H2 ; also sheet 2
I_MB08: A02.P2 B02.P2 ; also sheet 2
I_MB08\: A02.M2 B02.M2 ; also sheet 2
I_MB09: A02.S2 B02.S2 ; also sheet 2
I_MB10: A02.T2 B02.T2 ; also sheet 2
I_MB11: A02.V2 B02.V2 ; also sheet 2
I_MBINCR: A04.T2 B04.T2 ; also sheet 3
I_RUN: A03.S2 B03.S2 ; also sheet 1
I_SKIP: A03.K2 B03.K2 ; also sheet 3
I_TS1: A01.T2 B01.T2 ; also sheet 2
I_TS3: A01.S2 B01.S2 ; also sheet 2
I_TT_INST: A03.T2 B03.T2 ; also sheet 1
I_WCOV: A05.P2 B05.P2 ; also sheet 1

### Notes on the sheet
- Empty Slots:

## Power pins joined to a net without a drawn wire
-15V: A07.B2(-15V) A08.B2(-15V) A09.B2(-15V) A10.B2(-15V) A11.B2(-15V) A12.B2(-15V) B08.B2(-15V) B09.B2(-15V) B10.B2(-15V) B11.B2(-15V) B12.B2(-15V) B13.B2(-15V) B14.B2(-15V) B15.B2(-15V) B16.B2(-15V) B17.B2(-15V) B18.B2(-15V) B19.B2(-15V) B20.B2(-15V) B21.B2(-15V) B22.B2(-15V) B23.B2(-15V)
GND: A01.A1 A01.C1 A01.C2 A01.F1 A01.F2 A01.J2 A01.K1 A01.L2 A01.N1 A01.N2 A01.R1 A01.R2 A01.T1 A01.U2 A02.A1 A02.C1 A02.C2 A02.F1 A02.F2 A02.J2 A02.K1 A02.L2 A02.N1 A02.N2 A02.R1 A02.R2 A02.T1 A02.U2 A03.A1 A03.C1 A03.C2 A03.F1 A03.F2 A03.J2 A03.K1 A03.L2 A03.N1 A03.N2 A03.R1 A03.R2 A03.T1 A03.U2 A04.A1 A04.C1 A04.C2 A04.F1 A04.F2 A04.J2 A04.K1 A04.L2 A04.N1 A04.N2 A04.R1 A04.R2 A04.T1 A04.U2 A05.A1 A05.C1 A05.C2 A05.F1 A05.F2 A05.J2 A05.K1 A05.L2 A05.N1 A05.N2 A05.R1 A05.R2 A05.T1 A05.U2 A06.A1(GND) A06.C1(GND) A06.C2(GND) A06.F1(GND) A06.F2(GND) A06.J2(GND) A06.K1(GND) A06.L2(GND) A06.N1(GND) A06.N2(GND) A06.R1(GND) A06.R2(GND) A06.T1(GND) A06.U2(GND) A07.C2(GND) A08.C2(GND) A09.C2(GND) A10.C2(GND) A11.C2(GND) A12.C2(GND) A13.C2 A13.F2 A13.J2 A13.L2 A13.N2 A13.R2 A13.U2 A14.C2 A14.F2 A14.J2 A14.L2 A14.N2 A14.R2 A14.U2 A15.C2 A15.F2 A15.J2 A15.L2 A15.N2 A15.R2 A15.U2 A16.C2 A16.F2 A16.J2 A16.L2 A16.N2 A16.R2 A16.U2 A17.C2 A17.F2 A17.J2 A17.L2 A17.N2 A17.R2 A17.U2 A18.C2 A18.F2 A18.J2 A18.L2 A18.N2 A18.R2 A18.U2 A19.C2 A19.F2 A19.J2 A19.L2 A19.N2 A19.R2 A19.U2 A20.C2 A20.F2 A20.J2 A20.L2 A20.N2 A20.R2 A20.U2 A21.C2 A21.F2 A21.J2 A21.L2 A21.N2 A21.R2 A21.U2 A22.C2 A22.F2 A22.J2 A22.L2 A22.N2 A22.R2 A22.U2 A23.C2 A23.F2 A23.J2 A23.L2 A23.N2 A23.R2 A23.U2 B01.A1 B01.C1 B01.C2 B01.F1 B01.F2 B01.J2 B01.K1 B01.L2 B01.N1 B01.N2 B01.R1 B01.R2 B01.T1 B01.U2 B02.A1 B02.C1 B02.C2 B02.F1 B02.F2 B02.J2 B02.K1 B02.L2 B02.N1 B02.N2 B02.R1 B02.R2 B02.T1 B02.U2 B03.A1 B03.C1 B03.C2 B03.F1 B03.F2 B03.J2 B03.K1 B03.L2 B03.N1 B03.N2 B03.R1 B03.R2 B03.T1 B03.U2 B04.A1 B04.C1 B04.C2 B04.F1 B04.F2 B04.J2 B04.K1 B04.L2 B04.N1 B04.N2 B04.R1 B04.R2 B04.T1 B04.U2 B05.A1 B05.C1 B05.C2 B05.F1 B05.F2 B05.J2 B05.K1 B05.L2 B05.N1 B05.N2 B05.R1 B05.R2 B05.T1 B05.U2 B06.C2(GND) B06.T1(GND) B07.A1(GND) B07.C1(GND) B07.C2(GND) B07.F1(GND) B07.F2(GND) B07.J2(GND) B07.K1(GND) B07.L2(GND) B07.N1(GND) B07.N2(GND) B07.R1(GND) B07.R2(GND) B07.T1(GND) B07.U2(GND) B08.C2(GND) B09.C2(GND) B10.C2(GND) B11.C2(GND) B12.C2(GND) B13.C2(GND) B14.C2(GND) B15.C2(GND) B16.C2(C2:GND) B16.T2(T2:GND) B16.U2(U2:GND) B16.V2(V2:GND) B17.C2(C2:GND) B17.T2(T2:GND) B17.U2(U2:GND) B17.V2(V2:GND) B18.C2(C2:GND) B18.T2(T2:GND) B18.U2(U2:GND) B18.V2(V2:GND) B19.C2(C2:GND) B19.T2(T2:GND) B19.U2(U2:GND) B19.V2(V2:GND) B20.C2(C2:GND) B20.T2(T2:GND) B20.U2(U2:GND) B20.V2(V2:GND) B21.C2(C2:GND) B21.T2(T2:GND) B21.U2(U2:GND) B21.V2(V2:GND) B22.C2(C2:GND) B22.T2(T2:GND) B22.U2(U2:GND) B23.C2(C2:GND) B23.T2(T2:GND) B23.U2(U2:GND)
VCC: A06.A2(VCC) A07.A2(VCC) A08.A2(VCC) A09.A2(VCC) A10.A2(VCC) A11.A2(VCC) A12.A2(VCC) B06.A2(VCC) B07.A2(VCC) B08.A2(VCC) B09.A2(VCC) B10.A2(VCC) B11.A2(VCC) B12.A2(VCC) B13.A2(VCC) B14.A2(VCC) B15.A2(VCC) B16.A2(C2:VCC) B17.A2(C2:VCC) B18.A2(C2:VCC) B19.A2(C2:VCC) B20.A2(C2:VCC) B21.A2(C2:VCC) B22.A2(C2:VCC) B23.A2(C2:VCC)

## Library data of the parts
A01-A05 B01-B05 = dec-m:M903: Two-sided Posibus cable/connector.
A06 B07 = dec-m:M907: M907 Diode Clamp
A07-A09 A10-A12 B08 B09 B10-B15 = dec-m:M651: M651 - Negative Output Converter
A13-A23 = dec-m:W011: One-sided 9 pin connector/cable with grounds (Negibus).
A24 B24 = dec-m:H807: Empty card slot
B06 = dec-m:M101: Bus Data Interface The M101 contains 15 two-input NAND gates. One input of each gate is tied to a common line so that all data signals can be enabled simultaneously. Each data signal presents one TTL load. The common input presents 15 loads. Each output can drive 10 loads. Power: 5V@82ma (max.)
B16-B23 = dec-m:M517: M517 Negative Bus Converter

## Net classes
1 supply: width 0.381 mm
